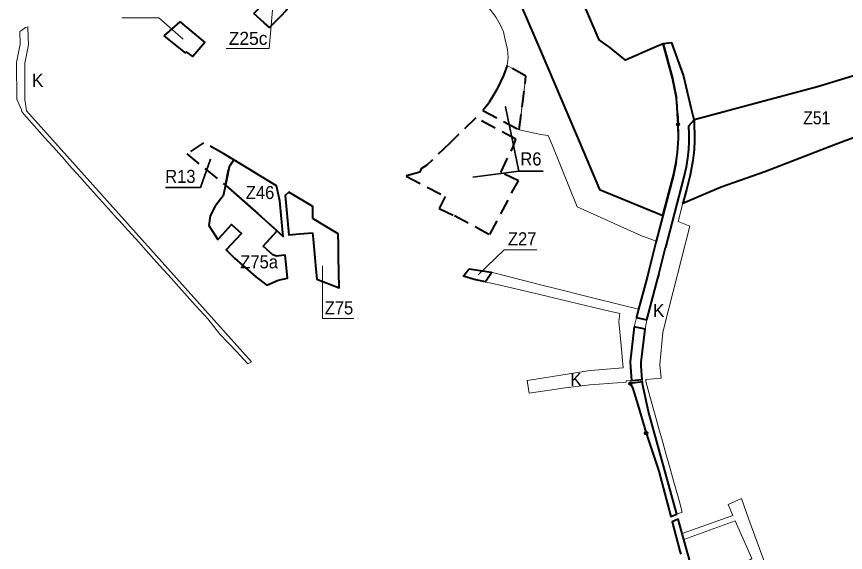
# Model space of a CAD drawing. Extents: x -650276 to -642489, y -1074311 to -1066658.
# Drawn here: x -650276 to -648750, y -1070699 to -1069712 of the extents above; entities that cross this region are included whole.
import ezdxf

# ---------------------------------------------------------------- set-up
doc = ezdxf.new("R2010")
doc.units = 0
doc.header["$LTSCALE"] = 9.6
doc.header["$PDMODE"] = 32
doc.header["$PDSIZE"] = 4.8
doc.linetypes.add('MEDIUM_DASHED', pattern=[4.5, 3, -1.5])
for name, color, linetype, lineweight in [('3', 7, 'Continuous', 40), ('44', 7, 'Continuous', 40), ('45', 7, 'Continuous', 40), ('46', 7, 'Continuous', 13), ('47', 7, 'Continuous', 13), ('48', 7, 'Continuous', 35), ('59', 7, 'Continuous', 13), ('61', 7, 'MEDIUM_DASHED', 40), ('62', 7, 'Continuous', 35)]:
    doc.layers.add(name, color=color, linetype=linetype, lineweight=lineweight)

msp = doc.modelspace()

# ---------------------------------------------------------------- linework, layer by layer
at = {"layer": '3'}
for points in [[(-649838.99, -1069706.15), (-649820.64, -1069687.33), (-649808.96, -1069675.34), (-649777.94, -1069699.2), (-649792.13, -1069713.65), (-649807.66, -1069729.46), (-649810.41, -1069732.28), (-649819.9, -1069723.61)], [(-650004.59, -1069747.27), (-649974.86, -1069721.96), (-649966.52, -1069728.87), (-649929.38, -1069759.65), (-649951.56, -1069785.42), (-649963, -1069776.7), (-649965, -1069778.7)], [(-649891.21, -1070022.68), (-649895.45, -1070042.15), (-649910.34, -1070061.29), (-649919.55, -1070079.01), (-649922.3, -1070096.9), (-649905.51, -1070122.35), (-649897.03, -1070113.07), (-649880.42, -1070094.87), (-649862.22, -1070111.54), (-649889.87, -1070141.83), (-649874.94, -1070157.19), (-649835.28, -1070191.27), (-649815.33, -1070206.63), (-649794.37, -1070197.2), (-649777.29, -1070193.57), (-649779.75, -1070168.69), (-649781.436, -1070151.591), (-649787.92, -1070152.23), (-649797.33, -1070153.41), (-649804.29, -1070150.68), (-649821.97, -1070134.58), (-649796.4, -1070106.56)], [(-649442.63, -1070176.69), (-649402.29, -1070182.92), (-649404.2, -1070187.43), (-649412.2, -1070200.71), (-649433.3, -1070195.89), (-649453.27, -1070190.02), (-649446.19, -1070180.76)]]:
    msp.add_lwpolyline(points, close=True, dxfattribs=at)
at = {"layer": '44'}
for p, q in [((-649058.858, -1069889.759), (-649057.868, -1069910.51)), ((-649057.134, -1069932.873), (-649057.868, -1069910.51)), ((-649146.163, -1070347.543), (-649145.424, -1070357.637))]:
    msp.add_line(p, q, dxfattribs=at)
for points in [[(-649061.138, -1069979.243), (-649061.138, -1069979.243), (-649061.139, -1069979.254), (-649066.487, -1070004.267), (-649098.65, -1070127.795), (-649110.925, -1070177.113), (-649114.174, -1070189.816), (-649130.712, -1070250.935), (-649134.294, -1070266.095), (-649115.159, -1070270.568), (-649095.152, -1070193.731), (-649093.095, -1070186.132), (-649095.152, -1070193.731), (-649080.924, -1070137.409), (-649080.38, -1070136.996), (-649047.131, -1070009.304), (-649042.468, -1069988.477), (-649042.468, -1069988.477), (-649039.966, -1069973.035), (-649037.98, -1069956.626), (-649037.322, -1069942.129), (-649037.137, -1069928.996), (-649037.665, -1069912.977), (-649028.017, -1069902.109), (-649032.928, -1069882.782), (-649048, -1069820), (-649069.4, -1069760.67), (-649085.41, -1069762.44), (-649068, -1069825.147), (-649060.897, -1069861.994)], [(-649138.43, -1070283.6), (-649146.163, -1070347.543), (-649146.163, -1070347.543)], [(-649125.503, -1070355.837), (-649126.069, -1070348.097), (-649118.257, -1070287.455), (-649138.43, -1070283.6)], [(-649145.424, -1070357.637), (-649143.633, -1070382.123), (-649123.693, -1070380.572), (-649125.503, -1070355.837)], [(-649059.951, -1070628.223), (-649112.14, -1070439.152), (-649123.138, -1070388.16), (-649123.385, -1070384.775), (-649145.73, -1070387.91)], [(-649145.73, -1070387.91), (-649141.48, -1070394.84), (-649132.07, -1070426.81), (-649116.56, -1070479.19)], [(-649116.56, -1070479.19), (-649093.2, -1070549.1), (-649071.33, -1070632.6), (-649059.951, -1070628.223)], [(-649025.129, -1070754.377), (-649047.11, -1070674.743), (-649050.081, -1070663.981), (-649057.338, -1070637.689), (-649068.65, -1070642.23), (-649068.65, -1070642.23), (-649054.31, -1070696.44), (-649052.77, -1070702.25)]]:
    msp.add_lwpolyline(points, dxfattribs=at)
for centre, radius, start, end in [((-649633.43, -1069918.001), 575.266, 2.81398, 5.58706), ((-649347.129, -1069931.193), 290, 350.46253, 4.08974), ((-649347.129, -1069931.193), 290, 359.66809, 4.08974)]:
    msp.add_arc(centre, radius, start, end, dxfattribs=at)
for p in [(-649145.73, -1070387.91), (-649116.56, -1070479.19)]:
    msp.add_point(p, dxfattribs=at)
at = {"layer": '45'}
msp.add_line((-649057.868, -1069910.51), (-649058.82, -1069890.548), dxfattribs=at)
for points in [[(-649364.44, -1069650.55), (-649312.03, -1069773.33), (-649246.81, -1069926.27), (-649246.81, -1069926.27), (-649239.635, -1069943.094), (-649202.375, -1070030.469), (-649202.375, -1070030.469), (-649085.737, -1070078.201), (-649066.487, -1070004.267), (-649061.139, -1069979.254), (-649061.138, -1069979.243), (-649061.138, -1069979.243)], [(-649060.897, -1069861.994), (-649068, -1069825.147), (-649085.41, -1069762.44), (-649085.41, -1069762.44), (-649099.75, -1069768.575), (-649154.76, -1069792.11), (-649184.05, -1069768.45), (-649200.64, -1069756.53), (-649202.99, -1069754.99), (-649241.11, -1069665.9)], [(-648722.24, -1069817.54), (-648772.48, -1069832.83), (-648800.85, -1069841.52), (-648906.547, -1069869.711), (-649007.37, -1069896.602), (-649028.017, -1069902.109), (-649027.457, -1069939.468), (-649028.007, -1069957.455), (-649030.869, -1069977.253), (-649035.775, -1070004.354), (-649042.536, -1070031.342), (-649048.918, -1070055.852), (-648978.654, -1070025.669), (-648897.735, -1069997.25), (-648767.83, -1069946.87), (-648562.242, -1069870.301)], [(-649730.837, -1070084.028), (-649730.6, -1070061.98), (-649774.73, -1070035.58), (-649781.53, -1070041.2), (-649774.45, -1070113.92), (-649754.82, -1070111.89), (-649731.12, -1070109.96)], [(-649730.837, -1070084.028), (-649730.6, -1070061.98), (-649774.73, -1070035.58), (-649781.53, -1070041.2), (-649774.45, -1070113.92), (-649754.82, -1070111.89), (-649731.12, -1070109.96)], [(-649731.12, -1070109.96), (-649730.57, -1070115.76), (-649730, -1070122.01), (-649726.22, -1070162.75), (-649725.49, -1070170.64), (-649723.17, -1070195.81), (-649682.04, -1070211.58), (-649683.12, -1070154.14), (-649682.98, -1070132.1), (-649683.57, -1070112.05), (-649717.72, -1070091.61), (-649730.837, -1070084.028)], [(-649731.12, -1070109.96), (-649730.57, -1070115.76), (-649730, -1070122.01), (-649726.22, -1070162.75), (-649725.49, -1070170.64), (-649723.17, -1070195.81), (-649682.04, -1070211.58), (-649683.12, -1070154.14), (-649682.98, -1070132.1), (-649683.57, -1070112.05), (-649717.72, -1070091.61), (-649730.837, -1070084.028)]]:
    msp.add_lwpolyline(points, dxfattribs=at)
msp.add_lwpolyline([(-649891.21, -1070022.68), (-649832.007, -1070074.751), (-649784.87, -1070116.76), (-649791.31, -1070051.51), (-649797.45, -1070023.77), (-649876.31, -1069975.93), (-649884.59, -1069988.57)], close=True, dxfattribs=at)
msp.add_lwpolyline([(-649891.21, -1070022.68), (-649832.007, -1070074.751), (-649784.87, -1070116.76), (-649791.31, -1070051.51), (-649797.45, -1070023.77), (-649876.31, -1069975.93), (-649884.59, -1069988.57)], close=True, dxfattribs=at)
for centre, radius, start, end in [((-649649.71, -1069919.176), 591.583, 2.77379, 5.54687), ((-649347.129, -1069931.193), 290, 350.46253, 4.08974)]:
    msp.add_arc(centre, radius, start, end, dxfattribs=at)
msp.add_point((-649057.868, -1069910.51), dxfattribs=at)
at = {"layer": '46'}
msp.add_lwpolyline([(-649654.738, -1070267.746), (-649712.819, -1070267.746), (-649712.819, -1070267.746), (-649712.586, -1070171.248)], dxfattribs=at)
at = {"layer": '47'}
msp.add_line((-649115.159, -1070270.568), (-649118.257, -1070287.455), dxfattribs=at)
for points in [[(-649538.49, -1069541.54), (-649527.84, -1069552.16), (-649517.81, -1069563.27), (-649507.23, -1069573.85), (-649474.46, -1069613.59), (-649415.12, -1069685.26), (-649401.77, -1069701.47), (-649392.85, -1069713.53), (-649385.25, -1069726.48), (-649379.49, -1069740.04), (-649376.01, -1069754.58), (-649372.2, -1069772.58), (-649370.94, -1069787.45), (-649372.56, -1069802.33), (-649372.56, -1069802.33), (-649338, -1069822), (-649350.222, -1069920.873), (-649310.738, -1069929.342), (-649296.851, -1069931.092)], [(-649202.375, -1070030.469), (-649239.635, -1069943.094), (-649246.81, -1069926.27), (-649246.81, -1069926.27), (-649312.03, -1069773.33), (-649364.44, -1069650.55), (-649379.32, -1069615.71)], [(-650260.665, -1069868.303), (-650260.748, -1069867.327), (-650261.204, -1069797.969), (-650254.411, -1069764.006), (-650255.21, -1069733.253), (-650255.716, -1069731.162), (-650259.97, -1069732.29), (-650264.91, -1069735.69), (-650270.059, -1069739.232)], [(-650270.059, -1069739.232), (-650269.449, -1069762.714), (-650276.214, -1069796.532), (-650275.76, -1069865.474), (-650274.95, -1069865.62)], [(-650274.95, -1069865.62), (-650273.61, -1069868.62), (-650266.89, -1069883.7)], [(-650266.89, -1069883.7), (-650266.68, -1069886.78), (-650262.64, -1069891.57), (-650257.16, -1069898.07), (-650224.71, -1069934.41), (-650209.51, -1069951.43), (-650192.51, -1069970.47), (-650174.3, -1069990.86), (-650157.87, -1070009.26), (-650151.03, -1070016.84), (-650134.26, -1070035.45), (-650106.76, -1070065.96), (-650091.89, -1070082.46), (-650087.18, -1070087.68), (-650076.72, -1070099.29), (-650051.33, -1070127.45), (-650037.78, -1070142.48), (-650018.41, -1070163.97), (-650005.3, -1070178.51), (-649990.95, -1070194.43), (-649977.05, -1070209.85), (-649946.39, -1070243.87), (-649930.46, -1070261.54), (-649924.15, -1070268.55), (-649913.03, -1070282.44), (-649901.59, -1070296.73), (-649871.28, -1070329.01), (-649850.04, -1070351.64), (-649843.513, -1070347.685), (-650257.713, -1069885.547), (-650260.665, -1069868.303)], [(-649057.722, -1070089.665), (-649048.918, -1070055.852), (-649037.411, -1070011.659), (-649032.972, -1069991.835), (-649028.007, -1069957.455), (-649027.566, -1069943.013), (-649027.135, -1069928.902), (-649027.569, -1069915.721), (-649028.017, -1069902.109), (-649037.665, -1069912.977), (-649037.137, -1069928.996), (-649037.199, -1069933.38), (-649037.322, -1069942.129), (-649037.98, -1069956.626), (-649039.623, -1069970.202), (-649042.468, -1069988.477), (-649047.131, -1070009.304), (-649055.689, -1070042.169), (-649061.354, -1070063.169), (-649067.061, -1070085.844), (-649079.268, -1070132.727), (-649080.38, -1070136.996), (-649080.872, -1070137.37), (-649083.089, -1070145.979)], [(-649296.851, -1069931.092), (-649289.95, -1069948.146), (-649243.846, -1070062.071), (-649126.437, -1070115.217), (-649126.437, -1070115.217), (-649098.101, -1070125.688), (-649085.737, -1070078.201), (-649202.375, -1070030.469)], [(-649089.07, -1070377.88), (-649091.46, -1070352.73), (-649086.157, -1070293.589), (-649082.233, -1070278.265), (-649036.031, -1070097.854), (-649057.722, -1070089.665)], [(-649083.089, -1070145.979), (-649095.152, -1070193.731), (-649093.095, -1070186.132), (-649095.152, -1070193.731), (-649111.303, -1070255.758), (-649095.152, -1070193.731), (-649115.159, -1070270.568)], [(-649118.257, -1070287.455), (-649126.069, -1070348.097), (-649125.503, -1070355.837), (-649123.693, -1070380.572)], [(-649123.693, -1070380.572), (-649123.385, -1070384.775), (-649123.138, -1070388.16), (-649112.14, -1070439.152), (-649059.951, -1070628.223), (-649049.96, -1070624.38), (-649055.93, -1070603.08), (-649058.38, -1070594.33), (-649065.42, -1070569.21), (-649072.47, -1070544.09), (-649079.51, -1070518.97), (-649086.55, -1070493.85), (-649093.59, -1070468.73), (-649100.01, -1070445.82), (-649102.31, -1070437.61), (-649109.76, -1070411.05), (-649117.36, -1070383.93), (-649117.374, -1070380.081), (-649089.07, -1070377.88)]]:
    msp.add_lwpolyline(points, dxfattribs=at)
for points in [[(-649159.19, -1070358.82), (-649197.91, -1070361.8), (-649203.4, -1070362.23), (-649220.47, -1070363.94), (-649231.39, -1070365.69), (-649273.57, -1070372.44), (-649304.18, -1070377.35), (-649331.3, -1070381.69), (-649335.79, -1070382.41), (-649332.2, -1070405.42), (-649294.79, -1070399.65), (-649269.769, -1070396.502), (-649220.16, -1070390.26), (-649202.969, -1070388.965), (-649153.11, -1070385.21), (-649153.64, -1070382.9), (-649143.633, -1070382.123), (-649146.163, -1070347.543), (-649138.43, -1070283.6), (-649134.294, -1070266.095), (-649130.712, -1070250.935), (-649160.748, -1070243.413), (-649220.52, -1070228.443), (-649288.379, -1070211.449), (-649310.998, -1070205.784), (-649342.149, -1070197.982), (-649402.29, -1070182.92), (-649404.2, -1070187.43), (-649412.2, -1070200.71), (-649408.24, -1070201.62), (-649391.184, -1070205.516), (-649372.69, -1070209.74), (-649335.914, -1070218.359), (-649299.227, -1070226.958), (-649289.83, -1070229.16), (-649197.55, -1070251.65), (-649164.91, -1070258.55), (-649166.86, -1070273.48), (-649162.91, -1070317.47)], [(-649014.888, -1070782.994), (-648966.35, -1070764.7), (-648908.94, -1070740.19), (-648892.215, -1070733.293), (-648927.2, -1070637.98), (-648941.064, -1070599.735), (-648965.569, -1070610.382), (-648956.687, -1070630.825), (-649050.081, -1070663.981), (-649047.11, -1070674.743), (-648952.455, -1070640.564), (-648922.196, -1070710.207), (-648924.668, -1070712.022), (-648943.837, -1070720.104), (-649025.129, -1070754.377)]]:
    msp.add_lwpolyline(points, close=True, dxfattribs=at)
at = {"layer": '59'}
msp.add_line((-649377.965, -1070141.64), (-649426.071, -1070187.689), dxfattribs=at)
for points in [[(-649890.273, -1069770.557), (-649810.727, -1069770.557), (-649804.906, -1069700.153), (-649810.727, -1069770.557), (-649810.727, -1069770.557)], [(-650082.06, -1069714.05), (-650014.296, -1069714.05), (-650014.296, -1069714.05), (-649969.577, -1069753.88)], [(-649318.08, -1070141.64), (-649318.08, -1070141.64), (-649377.965, -1070141.64), (-649377.965, -1070141.64)]]:
    msp.add_lwpolyline(points, dxfattribs=at)
at = {"layer": '61'}
for points in [[(-649372.56, -1069802.33), (-649379.19, -1069820.24), (-649391.86, -1069846.18), (-649406.53, -1069871.59), (-649417.234, -1069885.193), (-649350.222, -1069920.873), (-649338, -1069822)], [(-649430.515, -1069898.514), (-649479.08, -1069945.53), (-649520.6, -1069985.72), (-649530.31, -1069991.5), (-649530.99, -1069991.9), (-649533.61, -1069998.6), (-649557.92, -1070005.19), (-649558.56, -1070006.13), (-649486.5, -1070043.26), (-649497.95, -1070065.49), (-649469.85, -1070078.3), (-649404.76, -1070113.41), (-649360.74, -1070030.35), (-649351.66, -1070014.26), (-649384.249, -1069998.959), (-649361.46, -1069951.93), (-649356.458, -1069937.945)], [(-649931.76, -1069944.31), (-649962.859, -1069964.896), (-649891.21, -1070022.68), (-649884.59, -1069988.57), (-649876.31, -1069975.93), (-649894.68, -1069964.78)]]:
    msp.add_lwpolyline(points, close=True, dxfattribs=at)
at = {"layer": '62'}
for points in [[(-649306.343, -1069996.537), (-649351.328, -1069996.537), (-649375.864, -1069878.046), (-649351.328, -1069996.537), (-649435.663, -1070007.798)], [(-650001.823, -1070026.616), (-649937.373, -1070026.616), (-649918.861, -1069974.471)]]:
    msp.add_lwpolyline(points, dxfattribs=at)
at = {"layer": '62', "lineweight": 13}
msp.add_lwpolyline([(-650001.823, -1070026.616), (-649937.373, -1070026.616), (-649918.861, -1069974.471)], dxfattribs=at)

# ---------------------------------------------------------------- texts
at = {"layer": '46'}
for s, width, p in [('Z51', 0.9, (-648827.214, -1069910.388)), ('Z46', 0.95, (-649853.994, -1070048.002)), ('Z46', 0.95, (-649853.994, -1070048.002)), ('Z75', 0.95, (-649708.673, -1070260.465))]:
    msp.add_text(s, height=24, dxfattribs=dict(at, width=width)).set_placement(p)
at = {"layer": '48'}
for p in [(-650248.205, -1069841.413), (-650248.205, -1069841.413), (-649104.211, -1070265.34), (-649256.486, -1070392.051)]:
    msp.add_text('K', height=24, dxfattribs=at).set_placement(p)
at = {"layer": '59'}
msp.add_text('Z25c', height=24, dxfattribs=at).set_placement((-649885.454, -1069764.184))
at = {"layer": '59', "width": 0.95}
for s, p in [('Z27', (-649371.182, -1070133.176)), ('Z75a', (-649864.164, -1070175.692))]:
    msp.add_text(s, height=24, dxfattribs=at).set_placement(p)
at = {"layer": '62', "width": 0.95}
for s, p in [('R6', (-649348.349, -1069986.108)), ('R13', (-650002.521, -1070018.261)), ('R13', (-650002.521, -1070018.261))]:
    msp.add_text(s, height=24, dxfattribs=at).set_placement(p)

doc.saveas('drawing.dxf')
